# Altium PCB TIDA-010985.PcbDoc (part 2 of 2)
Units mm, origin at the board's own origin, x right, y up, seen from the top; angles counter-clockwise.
Board outline 125.73 x 87.63 mm, 4 copper layers (Top Layer, Signal Layer 1, Signal Layer 2, Bottom Layer), stack 1.565 mm thick; 149 components, 77 nets, 379 pads, 230 vias.
Unrouted connection lines stored in the file: 1.
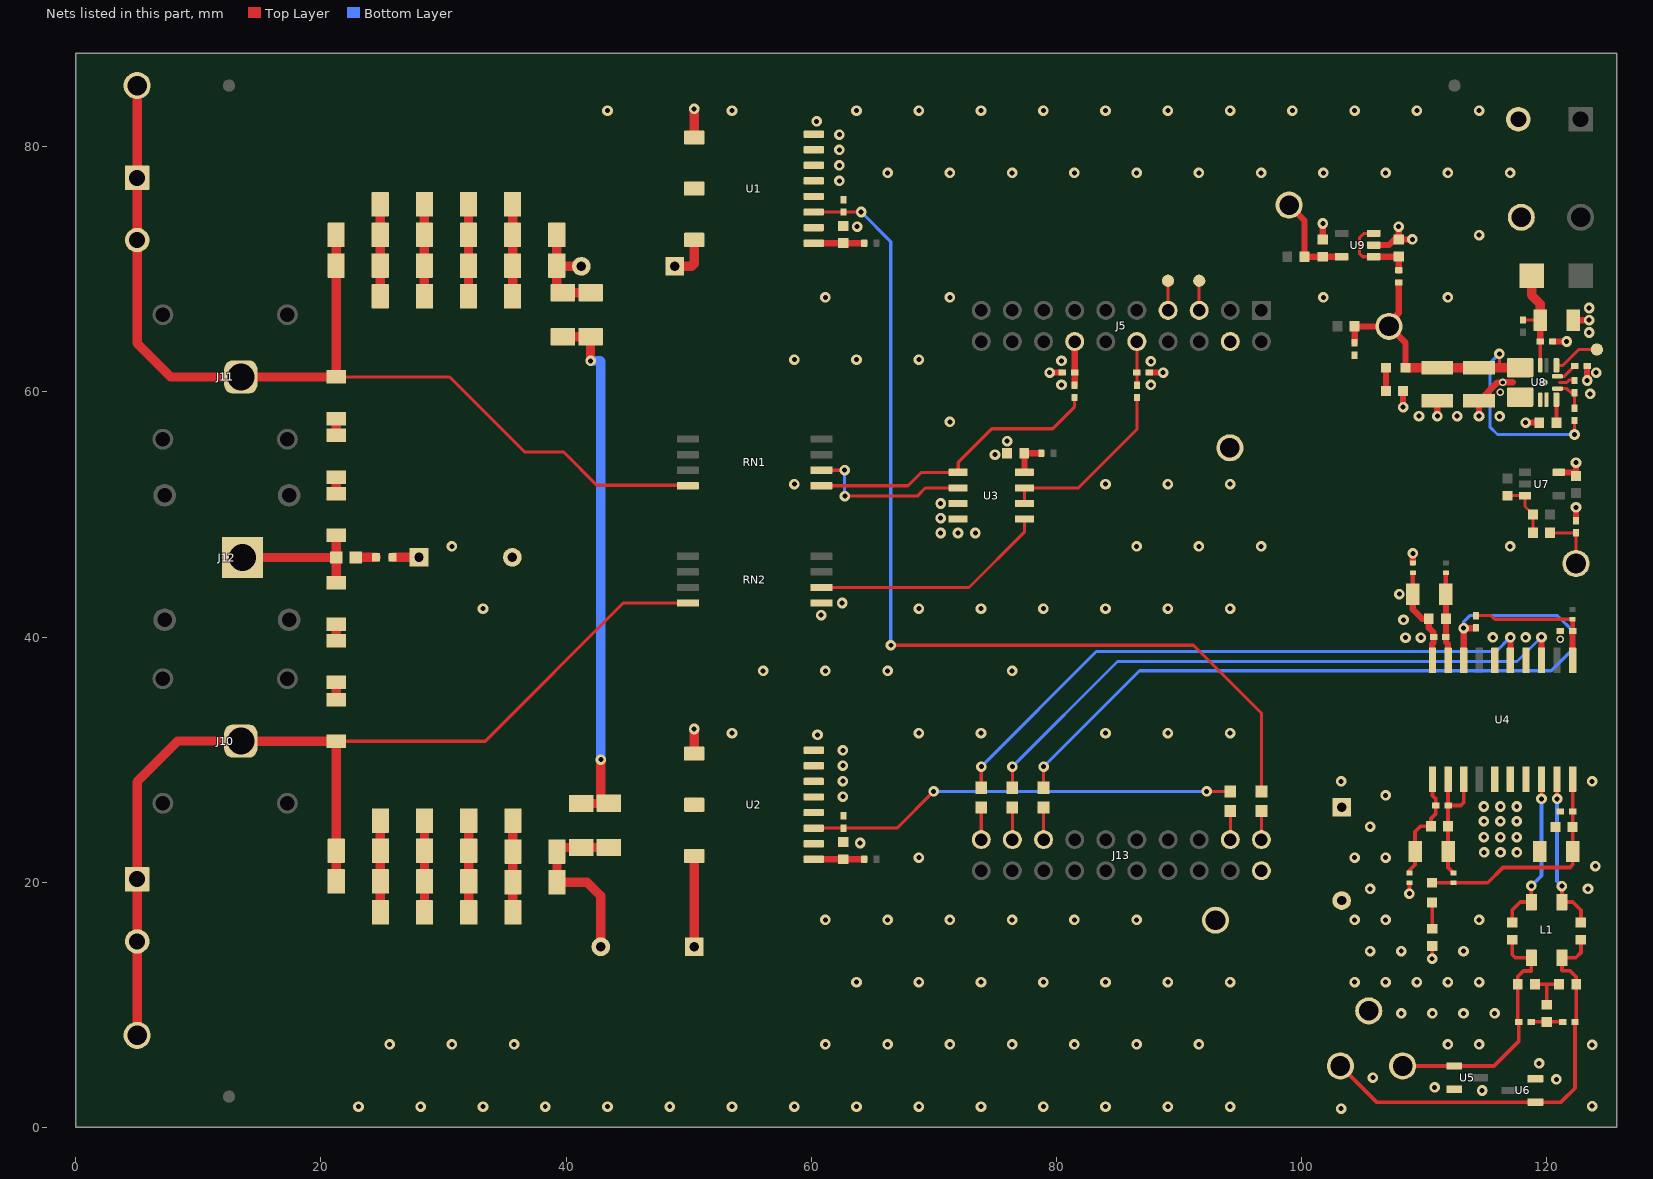
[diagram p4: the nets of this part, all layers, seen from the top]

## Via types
v1: diameter 0.864, hole 0.406, Top Layer to Bottom Layer, tented both sides, 225 vias
v2: diameter 0.61, hole 0.356, Top Layer to Bottom Layer, tented both sides, 5 vias

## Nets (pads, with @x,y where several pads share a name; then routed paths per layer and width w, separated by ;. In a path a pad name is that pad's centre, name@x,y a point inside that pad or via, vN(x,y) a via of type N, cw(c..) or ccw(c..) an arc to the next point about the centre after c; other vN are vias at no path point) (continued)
BUCK_FB: R48.1 R50.2 U8.9 | length 2.8
  Top Layer w0.254: U8.9@120.9,60.273 121.669,60.273 122.009,59.933 R50.2@122.292,59.933 R48.1@122.292,58.673
BUCK_MODE: R49.1 U8.11 | length 1.8
  Top Layer w0.254: U8.11@120.9,61.273 121.463,61.273 R49.1@122.317,62.127
BUCK_OUT: C33.1 C34.1 C35.2 D3.2 FB13.1 R48.2 R52.1 TP3.1 U8.4 | length 37.1
  Top Layer w0.254: 116.158,61.973 v1(116.158,63.113) ; v1(122.292,56.525) R48.2@122.292,57.673
  Top Layer w0.508: C35.2@104.35,64.002 R52.1@104.35,65.352 TP3.1@107.15,65.352 ; FB13.1@107.942,68.929 107.942,66.441 107.15,65.65 TP3.1@107.15,65.352 ; D3.2@108.509,61.973 D3.2@108.5,61.982 108.5,64.002 TP3.1@107.15,65.352
  Top Layer w0.762: D3.2@108.509,61.973 C34.1@111.092,61.973 C33.1@114.5,61.973 116.158,61.973 U8.4@117.85,61.973
  Bottom Layer w0.254: v1(116.158,63.113) 115.388,62.344 115.388,57.149 116.013,56.525 v1(122.292,56.525)
BUCK_PGOOD: TP12.1 U8.1 | length 3.9
  Top Layer w0.254: U8.1@120.882,62.243 U8.1@120.812,62.173 121.35,62.173 122.637,63.459 TP12.1@124.114,63.459
BUCK_VCC: C28.2 U8.8 | length 1.9
  Top Layer w0.305: C28.2@120.812,57.5 U8.8@120.812,59.373
BUCK_VIN: C29.1 C30.2 D2.1 R44.2 U8.3 | length 9.1
  Top Layer w0.254: R44.2@118.08,65.877 119.475,65.877 C29.1@119.5,65.852
  Top Layer w0.305: U8.3@119.5,62.173 119.5,62.503 C30.2@119.5,64.116
  Top Layer w0.508: C30.2@119.5,64.116 C29.1@119.5,65.852
  Top Layer w0.762: D2.1@118.79,69.5 118.79,67.885 119.5,67.175 C29.1@119.5,65.852
CAN_EN: R26.1 R37.1 U4.8 | length 64.1
  Top Layer w0.254: R37.1@78.964,27.7 v1(78.964,29.424)
  Top Layer w0.508: U4.8@113.247,38.1 v1(113.247,40.725) 114.225,40.725 R26.1@114.25,40.75
  Bottom Layer w0.254: v1(78.964,29.424) 86.791,37.25 120.387,37.25 122.137,39 122.137,40.513 120.9,41.75 113.75,41.75 113.247,41.247 v1(113.247,40.725)
CAN_GND1: C6.2 C7.2 C8.2 C12.2 FB12.2 U4.4 U4.6 U4.10 | length 8.2
  Top Layer w0.381: C6.2@109.097,43.5 FB12.2@109.097,45.25
  Top Layer w0.508: C6.2@109.097,43.5 109.097,42.255 109.852,41.5 C7.2@110.397,41.5 110.397,40.746 110.793,40.35 C8.2@110.793,40 110.793,39.544 110.672,39.423 110.672,38.135 U4.10@110.707,38.1
  other v1: 108.499,39.953 109.749,39.953 115.624,39.977 118.307,39.977 108.337,41.41 108,43.504
  other v2: 121.137,39.821
CAN_GND2: C13.2 C14.2 C15.2 FB11.1 U4.11 | length 9.2
  Top Layer w0.305: FB11.1@108.822,20.75 108.822,20.963 109.277,21.418 C15.2@109.277,22.5 109.277,24.107 109.725,24.555 C14.2@110.577,24.555 110.577,25.192 110.977,25.592 C13.2@110.977,26.25 110.977,26.777 110.707,27.047 U4.11@110.707,28.4
CAN_VDD: C6.1 C7.1 C8.1 FB8.2 U4.9 | length 7.2
  Top Layer w0.381: C6.1@111.793,43.504 FB8.2@111.793,45.25
  Top Layer w0.508: C6.1@111.793,43.504 C6.1@111.797,43.5 C7.1@111.797,41.5 111.793,41.496 C8.1@111.793,40 111.793,39.607 111.977,39.423 U4.9@111.977,38.1
CAN_VIO: C12.1 FB9.2 R26.2 U4.1 | length 11.4
  Top Layer w0.254: R26.2@114.25,41.75 115.475,41.75 115.774,41.451 FB9.2@122.137,41.451
  Top Layer w0.381: C12.1@122.137,40.5 FB9.2@122.137,41.451
  Top Layer w0.508: U4.1@122.137,38.1 C12.1@122.137,40.5
CANH: L1.1 R27.2 U4.19 | length 13
  Top Layer w0.305: v1(120.867,26.792) U4.19@120.867,28.4 ; v1(121.266,19.68) L1.1@121.266,18.374 122.143,18.374 122.816,17.701 R27.2@122.816,16.7
  Bottom Layer w0.305: v1(120.867,26.792) 120.867,20.079 v1(121.266,19.68)
CANHI: C16.1 L1.4 R27.1 R28.2 TP13.1 U6.1 | length 35.1
  Top Layer w0.305: TP13.1@103.184,5 106.134,2.05 U6.1@119.1,2.05 121.196,2.05 122.336,3.19 C16.1@122.336,8.6 122.438,8.701 R28.2@122.438,11.672 122.438,12.262 121.934,12.766 121.318,12.766 121.266,12.818 L1.4@121.266,13.824 122.389,13.824 122.816,14.25 R27.1@122.816,15.3
CANL: L1.2 R30.2 U4.18 | length 13.2
  Top Layer w0.305: R30.2@117.216,16.7 117.216,17.729 117.86,18.374 L1.2@118.766,18.374 v1(118.766,19.69) ; v1(119.597,26.792) U4.18@119.597,28.4
  Bottom Layer w0.305: v1(118.766,19.69) 119.597,20.522 v1(119.597,26.792)
CANLO: C18.2 L1.3 R29.1 R30.1 TP14.1 U5.1 | length 20.9
  Top Layer w0.305: TP14.1@108.264,5 U5.1@112.477,5 115.71,5 117.75,7.04 C18.2@117.75,8.6 117.656,8.694 R29.1@117.656,11.672 117.656,12.297 118.11,12.75 118.75,12.75 118.766,12.766 L1.3@118.766,13.824 117.476,13.824 117.216,14.084 R30.1@117.216,15.3
CANRX: R39.1 U4.5 | length 51.1
  Top Layer w0.254: R39.1@73.884,27.7 v1(73.884,29.424)
  Top Layer w0.508: U4.5@117.057,38.1 v1(117.057,39.977)
  Bottom Layer w0.254: v1(73.884,29.424) 83.277,38.816 115.896,38.816 v1(117.057,39.977)
CANTX: R38.1 U4.3 | length 51.2
  Top Layer w0.254: R38.1@76.424,27.7 v1(76.424,29.424)
  Top Layer w0.508: U4.3@119.597,38.1 v1(119.597,40)
  Bottom Layer w0.254: v1(76.424,29.424) 85.001,38 117.597,38 v1(119.597,40)
GND: C1.2 C2.2 C3.2 C4.2 C5.2 C19.2 C22.2 C27.1 C28.1 C29.2 C30.1 C31.2 C32.2 C33.2 C34.2 C35.1 FB12.1 J5.22 J9.2 J13.20 J14.2 R43.1 R49.2 R50.1 R51.1 RN2.5 TP5.1 TP6.1 TP7.1 U1.2 U1.4 U1.5 U1.6 U1.7 U1.8 U1.9 U2.2 U2.4 U2.5 U2.6 U2.7 U2.8 U2.9 U3.3 U3.4 U7.5 U8.10 U9.2 | length 29.9
  Top Layer w0.254: 121.08,60.773 121.65,60.773 121.837,60.96 122.265,60.96 R50.1@122.292,60.933
  Top Layer w0.508: v1(79.466,61.576) C22.2@80.504,61.576 ; C19.2@87.584,61.576 v1(88.718,61.576) ; C32.2@101.75,72.438 v1(101.75,73.746) ; U9.2@105.892,71.984 107.15,71.984 107.613,72.446 C31.2@107.942,72.446 ; v1(107.942,73.496) C31.2@107.942,72.446 ; v1(108.3,58.76) R51.1@108.3,60.077 ; v1(109.06,72.446) C31.2@107.942,72.446 ; FB12.1@109.097,46.05 v1(109.097,46.835) ; v1(111.092,58.025) C34.2@111.092,59.273 ; v1(114.5,58.025) C33.2@114.5,59.273 116,60.773 v2(116.425,60.773) ; v1(118.3,57.5) C28.1@119.412,57.5 ; C30.1@120.5,64.116 v1(121.65,64.116) ; U7.5@121,53.438 122.124,53.438 R43.1@122.412,53.15 v1(122.412,54.225) ; C29.2@122.2,65.852 v1(123.482,65.852) ; C27.1@122.412,49.5 v1(122.412,50.589) ; v1(123.317,60.933) R49.2@123.317,62.127
  Top Layer w0.533: v2(116.425,60.773) 117.234,60.773
  Top Layer w0.762: U2.9@50.46,30.485 v1(50.46,32.5) ; U1.9@50.46,80.757 v1(50.46,83.107)
  other v1: 23.063,1.676 28.143,1.676 33.223,1.676 38.303,1.676 43.383,1.676 48.463,1.676 53.543,1.676 58.623,1.676 63.703,1.676 68.783,1.676 73.863,1.676 78.943,1.676 84.023,1.676 89.103,1.676 94.183,1.676 25.603,6.756 30.683,6.756 35.763,6.756 61.163,6.756 66.243,6.756 71.323,6.756 76.403,6.756 81.483,6.756 86.563,6.756 91.643,6.756 63.703,11.836 68.783,11.836 73.863,11.836 78.943,11.836 84.023,11.836 89.103,11.836 94.183,11.836 61.163,16.916 66.243,16.916 71.323,16.916 76.403,16.916 81.483,16.916 86.563,16.916 68.783,21.996 64,23.193 62.582,26.972 62.582,28.242 62.582,29.5 62.582,30.75 60.521,32.025 53.543,32.156 68.783,32.156 73.863,32.156 84.023,32.156 89.103,32.156 94.183,32.156 56.083,37.236 61.163,37.236 66.243,37.236 76.403,37.236 60.816,41.786 33.223,42.316 68.783,42.316 73.863,42.316 78.943,42.316 84.023,42.316 89.103,42.316 94.183,42.316 62.537,42.775 30.683,47.396 86.563,47.396 91.643,47.396 96.723,47.396 117.043,47.396 70.566,48.493 71.981,48.493 73.395,48.493 70.566,49.696 70.566,50.898 58.623,52.476 84.023,52.476 89.103,52.476 94.183,52.476 75,54.885 76,55.981 71.323,57.556 109.6,58.025 112.722,58.025 116.175,58.008 123.567,59.841 80.428,60.573 87.718,60.585 124.05,61.576 87.718,62.503 80.428,62.541 58.623,62.636 63.703,62.636 68.783,62.636 123.482,64.852 123.482,66.852 61.163,67.716 71.323,67.716 101.803,67.716 111.963,67.716 114.503,72.796 63.75,73.496 62.307,77.222 66.243,77.876 71.323,77.876 76.403,77.876 81.483,77.876 86.563,77.876 91.643,77.876 96.723,77.876 101.803,77.876 106.883,77.876 111.963,77.876 117.043,77.876 62.307,78.492 62.307,79.75 62.307,81 60.443,82.083 43.383,82.956 53.543,82.956 63.703,82.956 68.783,82.956 73.863,82.956 78.943,82.956 84.023,82.956 89.103,82.956 94.183,82.956 99.263,82.956 104.343,82.956 109.423,82.956 114.503,82.956
  other v2: 116.236,59.964
GND_ISO_CAN: C9.2 C10.2 C11.2 C16.2 C17.1 C18.1 FB11.2 J4.1 J4.2 R25.1 TP15.1 U4.15 U4.16 U4.17 U5.2 U6.2 | length 4.5
  Top Layer w0.305: v1(108.822,19.056) FB11.2@108.822,19.95 ; v1(110.672,13.75) R25.1@110.672,14.799 ; C18.1@118.75,8.6 C17.1@120.016,8.6 C16.2@121.336,8.6
  other v1: 103.25,1.514 123.737,1.72 114.75,3 110.879,3.25 120.812,3.905 105.841,4.05 119.397,5.22 123.737,6.72 111.963,6.756 114.503,6.756 108.153,9.296 110.693,9.296 113.233,9.296 115.773,9.296 104.343,11.836 106.883,11.836 109.423,11.836 111.963,11.836 114.503,11.836 105.613,14.376 108.153,14.376 113.233,14.376 104.343,16.916 106.883,16.916 114.503,16.916 105.613,19.456 123.393,19.456 123.987,21.306 104.343,21.996 106.883,21.996 114.911,22.438 116.252,22.438 117.594,22.438 114.895,23.668 116.237,23.668 117.578,23.668 105.613,24.536 114.895,24.97 116.237,24.97 117.578,24.97 114.895,26.174 116.237,26.174 117.578,26.174 106.883,27.076 103.25,28.22 123.737,28.219
LDO_IN: C31.1 FB13.2 U9.1 U9.3 | length 7
  Top Layer w0.254: U9.1@105.892,71.034 104.998,71.034 104.75,71.281 104.75,72.593 105.09,72.934 U9.3@105.892,72.934
  Top Layer w0.508: U9.1@105.892,71.034 107.929,71.034 C31.1@107.942,71.047 FB13.2@107.942,69.929
LDO_OUT: C32.1 R46.1 TP4.1 U9.5 | length 7.8
  Top Layer w0.254: C32.1@101.75,71.038 C32.1@101.754,71.034
  Top Layer w0.508: TP4.1@99,75.25 100.25,74 R46.1@100.25,71.038 C32.1@101.75,71.038 ; C32.1@101.754,71.034 U9.5@103.292,71.034
MP_1: U1.10
MP_2: U2.10
NetC17_2: C17.2 R28.1 R29.2 | length 3.7
  Top Layer w0.305: R29.2@119.056,11.672 120,11.672 ; C17.2@120.016,10 120.016,11.656 120,11.672 ; R28.1@121.038,11.672 120,11.672
NetC20_2: C20.2 C23.1 | length 1.4
  Top Layer w0.762: C20.2@21.25,34.9 C23.1@21.25,36.3
NetC21_2: C21.2 C24.1 | length 1.4
  Top Layer w0.762: C24.1@21.25,56.45 C21.2@21.25,57.825
NetC23_2: C23.2 C25.1 | length 1.4
  Top Layer w0.762: C23.2@21.25,39.7 C25.1@21.25,41.05
NetC24_2: C24.2 C26.1 | length 1.3
  Top Layer w0.762: C26.1@21.25,51.7 C24.2@21.25,53.05
NetD1_1: D1.1 R25.2 | length 2.2
  Top Layer w0.305: R25.2@110.672,16.199 D1.1@110.672,18.35
NetD3_1: D3.1 R51.2 | length 1.9
  Top Layer w0.508: R51.2@106.9,60.077 D3.1@106.9,61.982
NetFB14_2: FB14.2 J9.1 | length 2.2
  Top Layer w0.762: FB14.2@25.85,46.5 J9.1@28,46.5
NetR1_2: R1.2 R2.1 R13.2 R14.1 | length 7.5
  Top Layer w0.762: R14.1@24.84,67.81 R13.2@24.84,70.31 R1.2@24.84,72.81 R2.1@24.84,75.31
NetR2_2: R2.2 R3.1 R14.2 R15.1 | length 7.5
  Top Layer w0.762: R14.2@28.44,67.81 R15.1@28.44,70.31 R3.1@28.44,72.81 R2.2@28.44,75.31
NetR3_2: R3.2 R4.1 R15.2 R16.1 | length 7.5
  Top Layer w0.762: R16.1@32.04,67.81 R15.2@32.04,70.31 R3.2@32.04,72.81 R4.1@32.04,75.31
NetR4_2: R4.2 R5.1 R16.2 R17.1 | length 7.5
  Top Layer w0.762: R16.2@35.64,67.81 R17.1@35.64,70.31 R5.1@35.64,72.81 R4.2@35.64,75.31
NetR6_2: R6.2 R7.1 R18.2 R19.1 | length 42.7
  Top Layer w0.762: R18.2@39.75,64.5 R6.2@42,64.5 v1(42,62.541) ; R19.1@41.25,26.423 42.75,26.423 42.84,26.512 v1(42.84,30)
  Bottom Layer w0.762: v1(42,62.541) 42.799,62.541 42.84,62.5 v1(42.84,30)
NetR8_2: R8.2 R9.1 R20.2 R21.1 | length 7.5
  Top Layer w0.762: R9.1@35.66,17.526 R8.2@35.66,20 R20.2@35.66,22.5 R21.1@35.66,25.026
NetR9_2: R9.2 R10.1 R21.2 R22.1 | length 7.5
  Top Layer w0.762: R9.2@32.06,17.526 R10.1@32.06,20.061 R22.1@32.06,22.561 R21.2@32.06,25.026
NetR10_2: R10.2 R11.1 R22.2 R23.1 | length 7.5
  Top Layer w0.762: R11.1@28.45,17.526 R23.1@28.45,25.019
NetR11_2: R11.2 R12.1 R23.2 R24.1 | length 7.5
  Top Layer w0.762: R11.2@24.85,17.526 R12.1@24.85,20.061 R24.1@24.85,22.561 R23.2@24.85,25.019
OPAMP_V+: C5.1 FB7.2 U3.8 | length 2.8
  Top Layer w0.508: C5.1@77.393,55 FB7.2@78.785,55 ; U3.8@77.4,53.438 C5.1@77.4,54.885
PA8_UART1-TX: J5.4 TP9.1 | length 2.4
  Top Layer w0.254: J5.4@89.124,66.656 TP9.1@89.124,69.069
PA9_UART1-RX: J5.3 TP8.1 | length 2.4
  Top Layer w0.254: J5.3@91.664,66.656 TP8.1@91.664,69.069
PA11: J13.33 R37.2 | length 2.6
  Top Layer w0.254: J13.33@78.964,23.476 R37.2@78.964,26.1
PA12_CAN-TX: J13.32 R38.2 | length 2.6
  Top Layer w0.254: J13.32@76.424,23.476 R38.2@76.424,26.1
PA13_CAN-RX: J13.31 R39.2 | length 2.6
  Top Layer w0.254: J13.31@73.884,23.476 R39.2@73.884,26.1
PA24_ADC0.3: C22.1 J5.27 R34.2 | length 3.6
  Top Layer w0.508: R34.2@81.504,60.547 C22.1@81.504,61.576 J5.27@81.504,64.116
PB1_TIMA1-C1: J13.39 R36.2 | length 2.3
  Top Layer w0.254: J13.39@94.204,23.476 R36.2@94.204,25.806
PB4_TIMA1-C0: J13.40 R35.2 | length 2.3
  Top Layer w0.254: J13.40@96.744,23.476 R35.2@96.744,25.806
PB18_ADC1.5: C19.1 J5.25 R33.2 | length 3.6
  Top Layer w0.254: R33.2@86.584,60.547 C19.1@86.584,61.576 J5.25@86.584,64.116
PE: C25.2 C26.2 J12.1 R45.1 | length 11.5
  Top Layer w0.762: J12.1@13.61,46.49 R45.1@21.24,46.49 R45.1@21.25,46.5 ; C25.2@21.25,44.45 R45.1@21.25,46.5 ; C26.2@21.25,48.3 R45.1@21.25,46.5
PE_R: FB14.1 R45.2 | length 1.7
  Top Layer w0.762: R45.2@22.84,46.49 22.85,46.5 FB14.1@24.5,46.5
S1_U1: J1.1 U1.11 | length 3.6
  Top Layer w0.762: J1.1@48.87,70.25 50.25,70.25 50.46,70.46 U1.11@50.46,72.417
S1_U2: J2.1 U2.11 | length 7.4
  Top Layer w0.762: J2.1@50.46,14.728 U2.11@50.46,22.145
SW_EN1: C3.1 R35.1 U1.3 | length 79.1
  Top Layer w0.254: U1.3@60.21,74.682 C3.1@62.632,74.682 v1(64.085,74.682) ; v1(66.5,39.331) 91.197,39.331 96.744,33.784 R35.1@96.744,27.406
  Bottom Layer w0.254: v1(64.085,74.682) 66.5,72.267 v1(66.5,39.331)
SW_EN2: C4.1 R36.1 U2.3 | length 35.2
  Top Layer w0.254: U2.3@60.21,24.41 C4.1@62.632,24.41 67.004,24.41 v1(70,27.406) ; v1(92.27,27.406) R36.1@94.204,27.406
  Bottom Layer w0.254: v1(70,27.406) v1(92.27,27.406)
TLV431_CAT: R40.2 R41.2 R42.2 U7.3 | length 4.7
  Top Layer w0.254: R40.2@116.824,51.538 U7.3@118.25,51.538 118.25,50.647 R42.2@118.897,50 R41.2@118.897,48.5
U3A_IN-: RN1.6 U3.2 | length 13.5
  Top Layer w0.254: RN1.6@60.835,53.615 v1(62.735,53.615) ; v1(62.75,51.5) 68.655,51.5 69.323,52.168 U3.2@72,52.168
  Bottom Layer w0.254: v1(62.735,53.615) 62.735,51.515 v1(62.75,51.5)
U3B_IN+: RN2.6 U3.5 | length 19.5
  Top Layer w0.254: RN2.6@60.835,44.046 72.888,44.046 77.4,48.558 U3.5@77.4,49.628
VBOOT: U8.7
VDC+: C20.1 J6.1 J6.2 J10.1 R12.2 R24.2 RN2.4 TP11.1 | length 83.1
  Top Layer w0.254: C20.1@21.25,31.5 33.404,31.5 44.68,42.776 RN2.4@49.935,42.776
  Top Layer w0.762: TP11.1@5,7.5 J6.2@5,15.16 J6.1@5,20.24 5,28.2 8.315,31.515 J10.1@13.46,31.515 13.475,31.5 C20.1@21.25,31.5 R24.2@21.25,22.561 R12.2@21.25,20.061
VDC-: C21.1 J7.1 J7.2 J11.1 R1.1 R13.1 RN1.4 TP10.1 | length 82.4
  Top Layer w0.254: C21.1@21.25,61.225 30.5,61.225 36.628,55.098 39.804,55.098 42.513,52.388 49.892,52.388 RN1.4@49.935,52.345
  Top Layer w0.762: TP10.1@5,85 J7.1@5,77.475 J7.2@5,72.395 5,63.975 7.75,61.225 J11.1@13.46,61.225 C21.1@21.25,61.225 21.25,70.3 R13.1@21.24,70.31 R1.1@21.24,72.81
VDD_U1: C1.1 FB1.2 U1.1 | length 4.1
  Top Layer w0.508: U1.1@60.21,72.142 62.735,72.142 FB1.2@64.335,72.142
VDD_U2: C2.1 FB2.2 U2.1 | length 4.1
  Top Layer w0.508: U2.1@60.21,21.87 C2.1@62.632,21.87 FB2.2@64.335,21.87
VEREF+: C27.2 R41.1 TP1.1 | length 4.6
  Top Layer w0.254: R41.1@120.297,48.5 C27.2@122.412,48.5 TP1.1@122.412,46
VISOOUT: C13.1 C14.1 C15.1 FB10.1 U4.12 U4.13 | length 11.1
  Top Layer w0.305: U4.12@111.977,28.4 C13.1@111.977,26.25 ; FB10.1@112.422,20.75 111.977,21.195 C15.1@111.977,22.5 C14.1@111.977,24.555 C13.1@111.977,26.25 ; U4.13@113.247,28.4 113.247,26.494 113.003,26.25 C13.1@111.977,26.25
VP_CAN: C9.1 C10.1 C11.1 D1.2 FB10.2 U4.20 | length 19.1
  Top Layer w0.305: D1.2@110.672,19.95 FB10.2@112.422,19.95 115.213,19.95 116.458,21.195 121.914,21.195 122.137,21.418 122.137,26.25 U4.20@122.137,28.4
VSENSE_NEG: R34.1 RN1.5 U3.1 | length 24.6
  Top Layer w0.254: RN1.5@60.835,52.345 67.907,52.345 69,53.438 U3.1@72,53.438 72,54.25 74.75,57 79.703,57 81.504,58.802 R34.1@81.504,59.547
VSENSE_POS: R33.1 U3.6 U3.7 | length 15
  Top Layer w0.254: U3.6@77.4,50.898 U3.7@77.4,52.168 81.806,52.168 86.584,56.946 R33.1@86.584,59.547
VSN_1: J1.2 R5.2 R6.1 R17.2 R18.1 | length 9.2
  Top Layer w0.762: R5.2@39.24,72.81 R17.2@39.24,70.31 ; J1.2@41.25,70.25 39.3,70.25 R17.2@39.24,70.31 ; R6.1@42,68.1 R18.1@39.75,68.1 39.24,68.61 R17.2@39.24,70.31
VSN_2: J2.2 R7.2 R8.1 R19.2 R20.1 | length 15.3
  Top Layer w0.762: J2.2@42.84,14.728 42.84,18.877 41.717,20 R8.1@39.26,20 R20.1@39.26,22.5 39.583,22.823 R19.2@41.25,22.823 R7.2@43.75,22.823
VSW: U8.5 U8.6 | length 0
  Top Layer w0.305: U8.5@117.849,59.572 U8.5@117.85,59.573
pads on no net: FID1.1 FID2.1 FID3.1 J5.2 J5.5 J5.6 J5.7 J5.8 J5.9 J5.10 J5.23 J5.24 J5.26 J5.28 J5.29 J5.30 J10.2 J10.3 J10.4 J10.5 J11.2 J11.3 J11.4 J11.5 J12.2 J12.3 J12.4 J12.5 J13.11 J13.12 J13.13 J13.14 J13.15 J13.16 J13.17 J13.18 J13.19 J13.34 J13.35 J13.36 J13.37 J13.38 LBL1.0 RN1.1 RN1.2 RN1.3 RN1.7 RN1.8 RN2.1 RN2.2 RN2.3 RN2.7 RN2.8 U4.2 U4.7 U4.14 U5.3 U6.3 U7.1 U7.2 U9.4

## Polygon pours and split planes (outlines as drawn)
GND_ISO_CAN on Top Layer "Top Layer-GND_ISO_CAN" (solid, pour order 18): 102.116,0 125.73,0 125.73,29.35 102.116,29.35
GND on Top Layer "Top Layer-GND" (solid, pour order 6): 97.478,44.616 125.73,44.616 125.73,45.493 125.73,87.001 97.75,87 59.75,87 59.75,0 97.478,0
CAN_GND1 on Top Layer "Top Layer-CAN_GND1" (solid, remove dead copper, pour order 8): 107.529,37.124 123,37.124 123,45.5 107.529,45.5
GND_ISO_CAN on Signal Layer 1 "Signal Layer 1-GND_ISO_CAN" (solid, pour order 16): 102.116,0.75 125,0.75 125,29.35 102.116,29.35
GND on Signal Layer 1 "Signal Layer 1-GND" (solid, pour order 2): 125.73,44.75 97.478,44.75 97.478,0 21.25,0 21.25,87.5 125.73,87.5
CAN_GND1 on Signal Layer 1 "Signal Layer 1-CAN_GND1" (solid, pour order 10): 107.529,37.124 123,37.124 123,44.616 107.529,44.616
GND_ISO_CAN on Signal Layer 2 "Signal Layer 2-GND_ISO_CAN" (solid, pour order 20): 102.116,0.75 125,0.75 125,29.35 102.116,29.35
GND on Signal Layer 2 "Signal Layer 2-GND" (solid, pour order 12): 125.5,44.629 97.478,44.629 97.478,0 21.02,0 21.02,87.5 125.5,87.5
CAN_GND1 on Signal Layer 2 "Signal Layer 2-CAN_GND1" (solid, pour order 14): 107.529,37.124 123,37.124 123,44.295 107.529,44.295
GND_ISO_CAN on Bottom Layer "Bottom Layer-GND_ISO_CAN" (solid, pour order 22): 102.116,0.75 125,0.75 125,29.35 102.116,29.35
GND on Bottom Layer "Bottom Layer-GND" (solid, pour order 24): 97.478,45 125.73,45 125.73,45.878 125.73,87.386 97.75,87.384 59.75,87.384 59.75,0.384 97.478,0.384

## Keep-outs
Keep-Out Layer:
  text ".Layer_Name" at 14.656,-21.806 h1.52

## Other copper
Top Layer:
  pour cut-out: 116.775,58.76 121.35,58.76 121.35,62.75 116.775,62.75
  pour cut-out: 117.632,13.349 122.329,13.349 122.329,18.735 117.632,18.735
  pour cut-out: 108.831,20.694 113.888,20.694 113.888,29.33 108.831,29.33
  text ".Layer_Name" at 14.656,-21.806 h1.52
Signal Layer 1:
  pour cut-out: 108.831,20.694 113.888,20.694 113.888,29.33 108.831,29.33
  pour cut-out: 117.632,13.349 122.329,13.349 122.329,18.735 117.632,18.735
Signal Layer 2:
  pour cut-out: 108.831,20.694 113.888,20.694 113.888,29.33 108.831,29.33
  pour cut-out: 117.632,13.349 122.329,13.349 122.329,18.735 117.632,18.735
Bottom Layer:
  pour cut-out: 108.831,20.694 113.888,20.694 113.888,29.33 108.831,29.33
  pour cut-out: 117.632,13.349 122.329,13.349 122.329,18.735 117.632,18.735
  text ".Layer_Name" at 14.656,-21.806 h1.52

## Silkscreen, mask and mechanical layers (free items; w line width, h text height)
Top Overlay:
  lines w0.1: 47.5,40 47.501,39.999
  lines w0.203: 89.124,62.503 47.5,62.503 47.5,40 84.999,39.999 91.664,46.664 91.664,62.503
  text "TPSI2240" at 51.535,83.25 h2.54
  text "INPUT PWR" at 98.604,83.25 h2.54
  text "RES DIV NETWORK" at 25.25,80.75 h1.91
  text "6-36V, 5W" at 98.75,80.413 h2.54
  text "-" at 10.75,77.75 h2.54 r270
  text "-" at 10.75,72.75 h2.54 r270
  text "VDC-" at 14.25,72.142 h2.54 r90
  text "UART / TX   RX" at 88,71.761 h1.52
  text "SSR1" at 53.051,68.31 h2.54
  text "5V" at 109.596,65.25 h2.54
  text "-" at 80.504,60.166 h2.54 r180
  text "RES60A" at 53,59 h2.54
  text "+" at 89,58.998 h2.54 r90
  text "ADC0" at 78.065,57.766 h1.52
  text "ADC1" at 86.065,57.766 h1.52
  text "GND" at 34.895,48 h2.54
  text "PE" at 24.7,47.969 h2.54
  text "TLV9002" at 75.25,46.75 h1.91
  text "3.3VREF" at 114.986,43.75 h1.52
  text "VOLTAGE SENSE" at 68.918,41.75 h1.91
  text "ISO CAN" at 104.5,37.25 h1.91 r270
  text "ISOW1044" at 107,37.25 h1.91 r270
  text "CANRX" at 74.064,33.312 h1.02 r90
  text "CANTX" at 76.659,33.312 h1.02 r90
  text "CANEN" at 79.357,33.312 h1.02 r90
  text "TPSI2240" at 51.547,33 h2.54
  text "EN2" at 90.5,32 h1.91
  text "EN1" at 97.551,32 h1.91
  text "+" at 11.75,19.69 h2.54 r90
  text "SSR2" at 52.75,17.845 h2.54
  text "VDC+" at 14.25,14.799 h2.54 r90
  text "+" at 11.75,14.5 h2.54 r90
  text "RES DIV NETWORK" at 25.25,11.75 h1.91
  text "VBUS 0-1kV" at 17.75,8 h2.54 r90
  text "'.PRJ_Number' .PCB_Rev" at 37.5,8 h2.75
  text "GND" at 104.75,6.72 h1.02
  text "CAN" at 92.962,4.106 h2.54
  text "CANH" at 102.116,2.05 h1.02
  text "CANL" at 107.25,2.05 h1.02
  text ".Layer_Name" at 14.656,-21.806 h1.52
Bottom Overlay:
  text ".Layer_Name" at 14.656,-21.806 h1.52
Top Paste:
  text ".Layer_Name" at 14.656,-21.806 h1.52
Bottom Paste:
  text ".Layer_Name" at 14.656,-21.806 h1.52
Top Solder:
  text ".Layer_Name" at 14.656,-21.806 h1.52
  text ".Layer_Name" at 14.656,-21.806 h1.52
Bottom Solder:
  text ".Layer_Name" at 14.656,-21.806 h1.52
Drill Guide:
  text ".Layer_Name" at 14.656,-21.806 h1.52
M1 Board Outline:
  the board outline again, w0.254
  text ".Layer_Name" at 14.656,-21.806 h1.52
M2 Board Dimensions:
  rectangle: 0,-6.985 3.175,-3.81
  rectangle: 3.175,-10.16 12.7,-6.985
  lines w0.178: 0,-6.985 25.4,-6.985 ; 3.175,-10.16 3.175,-3.81 ; 6.35,-10.16 6.35,-3.81 ; 12.7,-10.16 12.7,-3.81 ; 19.05,-10.16 19.05,-3.81 ; 0,-10.16 25.4,-10.16 25.4,-3.81 0,-3.81 0,-10.16
  text ".Layer_Name" at 14.656,-21.806 h1.52
M3 3D STEP Top:
  text ".Layer_Name" at 14.656,-21.806 h1.52
M4 3D STEP Bottom:
  text ".Layer_Name" at 14.656,-21.806 h1.52
M5 Assembly Top:
  lines w0.254: -7.417,-23.626 160.223,-23.626 ; -7.417,-18.462 160.274,-18.462 ; -7.417,-13.297 -7.417,-28.791 94.31,-28.791 160.274,-28.791 160.274,-13.297 -7.404,-13.297 -7.404,-28.791 32.614,-28.791 ; 55.194,-28.791 55.194,-13.297 ; 87.376,-18.462 87.376,-13.297 ; 108.712,-18.462 108.712,-13.297 ; 124.511,-28.956 124.511,-23.804
  text "COMPONENTS MARKED 'DNP' SHOULD NOT BE POPULATED." at 29.299,-8.09 h1.52
  text "ASSEMBLY VARIANT:" at 29.286,-11.024 h1.52
  text ".VariantName" at 55.601,-11.024 h1.52
  text "PCB VIEWED FROM TOP SIDE" at -5.804,-16.654 h1.52
  text "BOARD #:" at 57.099,-16.654 h1.52
  text ".PRJ_Number" at 70.955,-16.654 h1.52
  text "REV:" at 92.405,-16.654 h1.52
  text ".PCB_Rev" at 99.809,-16.654 h1.52
  text "SVN REV:" at 113.69,-16.654 h1.52
  text ".VersionControl_RevNumber" at 126.543,-16.654 h1.52
  text "TID #:" at 57.099,-21.819 h1.52
  text ".TID" at 70.955,-21.819 h1.52
  text "PLOT NAME =" at -5.804,-27.034 h1.52
  text ".plot_File_Name" at 14.656,-27.034 h1.52
  text "GENERATED    :" at 57.15,-27.034 h1.52
  text ".Print_Date" at 79.235,-27.034 h1.52
  text ".Print_Time" at 97.752,-27.034 h1.52
  text "TEXAS INSTRUMENTS" at 129.87,-27.034 h1.52
M6 Assembly Bottom:
  lines w0.254: -7.429,-18.474 160.261,-18.474 ; -7.379,-23.639 160.261,-23.639 ; 28.334,-28.969 28.334,-23.817 ; 44.133,-18.474 44.133,-13.31 ; 65.468,-18.474 65.468,-13.31 ; 97.65,-28.804 97.65,-13.31 ; 120.231,-28.804 160.249,-28.804 160.249,-13.31 -7.429,-13.31 -7.429,-28.804 58.534,-28.804 160.261,-28.804 160.261,-13.31
  text "COMPONENTS MARKED 'DNP' SHOULD NOT BE POPULATED." at 154.991,-8.077 h1.52
  text ".VariantName" at 128.473,-11.024 h1.52
  text "ASSEMBLY VARIANT:" at 154.864,-11.024 h1.52
  text ".VersionControl_RevNumber" at 26.302,-16.667 h1.52
  text "SVN REV:" at 39.154,-16.667 h1.52
  text ".PCB_Rev" at 53.035,-16.667 h1.52
  text "REV:" at 60.439,-16.667 h1.52
  text ".PRJ_Number" at 81.89,-16.667 h1.52
  text "BOARD #:" at 95.745,-16.667 h1.52
  text "PCB VIEWED FROM BOTTOM SIDE" at 158.648,-16.667 h1.52
  text ".TID" at 81.89,-21.831 h1.52
  text "TID #:" at 95.745,-21.831 h1.52
  text "TEXAS INSTRUMENTS" at 22.974,-27.047 h1.52
  text ".Print_Time" at 55.093,-27.047 h1.52
  text ".Print_Date" at 73.609,-27.047 h1.52
  text "GENERATED    :" at 95.694,-27.047 h1.52
  text ".plot_File_Name" at 138.189,-27.047 h1.52
  text "PLOT NAME =" at 158.648,-27.047 h1.52
M9 Title Sheet:
  drawing of 57 lines, arcs and shapes, not listed
  text "1" at 18.792,204.127 h1.78
  text "2" at 82.182,204.127 h1.78
  text "3" at 145.411,204.127 h1.78
  text "4" at 209.08,204.127 h1.78
  text "5" at 272.555,204.127 h1.78
  text "6" at 336.182,204.127 h1.78
  text "A" at -10.579,175.095 h1.78
  text "A" at 365.341,175.095 h1.78
  text "B" at -10.579,114.643 h1.78
  text "B" at 365.341,114.643 h1.78
  text "C" at -10.579,54.318 h1.78
  text "C" at 365.341,54.318 h1.78
  text "PROJECT TITLE:" at 288.125,7.048 h1.14
  text ".PRJ_Title" at 289.395,3.662 h1.78
  text "DESIGNED FOR:" at 288.125,-0.597 h1.14
  text ".PRJ_Customer" at 289.395,-4.153 h1.78
  text "D" at -10.579,-5.88 h1.78
  text "D" at 365.341,-5.88 h1.78
  text "FILE NAME:" at 288.125,-8.217 h1.14
  text ".PCB_File_Name_No_Path" at 289.395,-11.265 h1.78
  text "Texas Instruments (TI) and/or its licensors do not warrant the accuracy or completeness of this specification" at 161.9,-15.376 h1.14
  text "ENGINEER:" at 288.125,-15.583 h1.14
  text "LAYOUT BY:" at 326.352,-15.583 h1.14
  text "or any information contained therein. TI and/or its licensors do not warrant that this design will meet" at 160.757,-18.237 h1.14
  text ".PRJ_Engineer" at 289.395,-19.52 h1.78
  text ".PCB_Layout" at 327.635,-19.52 h1.78
  text "the specifications, will be suitable for your application or fit for any particular purpose, or will operate in" at 160.757,-21.099 h1.14
  text ".Layer_Name" at 14.656,-21.806 h1.52
  text "ALTIUM DESIGNER VERSION:" at 326.352,-23.457 h1.14
  text "an implementation. TI and/or its licensors do not warrant that the design is production worthy. You should" at 160.757,-23.961 h1.14
  text "completely validate and test your design implementation to confirm the system functionality for your application." at 161.9,-26.822 h1.14
  text ".print_Scale" at 289.395,-26.843 h1.78
  text ".Application_BuildNumber" at 327.635,-26.843 h1.78
  text "1" at 18.792,-32.093 h1.78
  text "2" at 82.182,-32.093 h1.78
  text "3" at 145.411,-32.093 h1.78
  text "4" at 209.08,-32.093 h1.78
  text "5" at 272.555,-32.093 h1.78
  text "6" at 336.182,-32.093 h1.78
M10 Fab Notes:
  drawing of 189 lines, arcs and shapes, not listed
  text "DESIGN INFORMATION" at 314.503,161.447 h1.52
  text "MIN. TRACK WIDTH:" at 298.131,158.091 h1.52
  text "10" at 325.976,158.091 h1.52
  text "MIL" at 329.907,158.091 h1.52
  text "MIN. CLEARANCE:" at 298.131,154.938 h1.52
  text "MIL" at 329.907,154.938 h1.52
  text "4.5" at 324.5,154.75 h1.52
  text "MIN. VIA PAD SIZE:" at 298.131,151.785 h1.52
  text "24" at 325.214,151.785 h1.52
  text "MIL" at 329.907,151.785 h1.52
  text "0.127mm (5MIL)" at 315.784,148.486 h1.52
  text "MINIMUM ANNULAR RING" at 289.769,148.277 h1.52
  text "EXTERNAL" at 333.768,148.277 h1.52
  text "PER" at 294.849,145.48 h1.52
  text "IPC-D-275 CLASS 2 LEVEL C" at 300.437,145.48 h1.52
  text "MIL, HOLES" at 338.238,142.928 h1.52
  text "+/-" at 328.27,142.709 h1.52
  text "+/-" at 349.961,142.709 h1.52
  text "REGISTRATION TOLERANCES:" at 289.769,142.682 h1.52
  text "METAL" at 320.243,142.682 h1.52
  text "5" at 334.879,142.683 h1.52
  text "3" at 356.037,142.683 h1.52
  text "MIL" at 358.99,142.682 h1.52
  text "HOLE SIZE TOLERANCE (UNLESS OTHERWISE SPECIFIED):" at 289.769,140.185 h1.52
  text "+/-" at 349.961,140.112 h1.52
  text "3" at 356.037,140.085 h1.52
  text "MIL" at 358.99,140.085 h1.52
  text "MATERIAL:" at 287.87,136.589 h1.52
  text "FR-4 High Tg" at 312.926,133.324 h1.52
  text "X" at 309.257,133.122 h1.52
  text "FR-4" at 298.563,133.007 h1.52
  text "OTHER" at 336.358,133.007 h1.52
  text "62 MIL (1.6mm) +/-10%" at 306.694,129.374 h1.52
  text "X" at 303.643,129.312 h1.52
  text "THICKNESS:" at 289.769,129.165 h1.52
  text "OTHER" at 339.33,129.165 h1.52
  text "TOLERANCE:" at 289.769,125.652 h1.52
  text "X" at 311.314,125.652 h1.52
  text "ANSI IPC-6012 TYPE 3 CLASS 2" at 315.836,125.652 h1.52
  text "OTHER +/-" at 315.835,121.989 h1.52
  text "BOW & TWIST:" at 289.769,118.302 h1.52
  text "X" at 311.314,118.302 h1.52
  text "ANSI IPC-6012 TYPE 3 CLASS 2" at 315.836,118.302 h1.52
  text "OTHER +/-" at 315.835,114.576 h1.52
  text "DRILLING:" at 287.87,111.258 h1.52
  text "NC_DRILL FILES" at 332.599,108.586 h1.52
  text "REFERENCE:" at 289.769,108.486 h1.52
  text "X" at 306.463,108.484 h1.52
  text "AS SHOWN" at 310.984,108.486 h1.52
  text "X" at 329.348,108.486 h1.52
  text "OTHER" at 340.168,104.873 h1.52
  text "PTH COPPER THICKNESS:" at 289.761,104.783 h1.52
  text "X" at 318.697,104.783 h1.52
  text "20-30 um" at 321.948,104.783 h1.52
  text "BOARD FINISH:" at 287.87,101.034 h1.52
  text "SILKSCREEN:" at 291.812,98.237 h1.52
  text "X" at 316.14,98.237 h1.52
  text "TOP" at 319.112,98.237 h1.52
  text "X" at 329.094,98.237 h1.52
  text "BOTTOM" at 332.091,98.237 h1.52
  text "SILKSCREEN COLOR:" at 291.812,94.295 h1.52
  text "X" at 316.115,94.295 h1.52
  text "WHITE" at 319.112,94.295 h1.52
  text "OTHER" at 332.091,94.295 h1.52
  text "X" at 319.442,90.652 h1.52
  text "GREEN" at 322.439,90.652 h1.52
  text "OTHER" at 338.136,90.652 h1.52
  text "SOLDER RESIST COLOR:" at 291.812,90.477 h1.52
  text "X" at 319.442,86.734 h1.52
  text "MATTE" at 322.439,86.734 h1.52
  text "SEMI-GLOSS" at 338.125,86.717 h1.52
  text "IMMERSION GOLD (ENIG)" at 314.819,82.345 h1.52
  text "ENEPIG" at 348.793,82.162 h1.52
  text "SURFACE FINISH:" at 287.87,82.136 h1.52
  text "X" at 310.298,82.136 h1.52
  text "IMM. TIN/SILVER OR EQUIV" at 296.24,78.649 h1.52
  text "OTHER" at 332.599,78.549 h1.52
  text "ARRAY/PANEL:" at 287.87,74.602 h1.52
  text "CUT AND TRIM PER M1 BOARD OUTLINE" at 314.819,74.393 h1.52
  text "N.C. ROUTE" at 314.819,70.94 h1.52
  text "X" at 332.295,70.94 h1.52
  text "V. SCORE" at 336.816,70.94 h1.52
  text "CERTIFICATION:" at 287.87,67.66 h1.52
  text "MATERIALS AND WORKMANSHIP FOR ALL PCBS" at 306.285,67.66 h1.52
  text "TO MEET OR EXCEED THE REQUIREMENTS OF:" at 306.285,65.271 h1.52
  text "X" at 297.078,62.003 h1.52
  text "ANSI IPC-A-600F CLASS ->" at 300.329,62.003 h1.52
  text "X" at 342.188,62.003 h1.52
  text "2" at 344.982,62.003 h1.52
  text "1" at 336.981,61.965 h1.52
  text "3" at 353.973,61.965 h1.52
  text "X" at 317.702,58.252 h1.52
  text "RoHS" at 320.953,58.252 h1.52
  text "OTHER" at 337.321,58.252 h1.52
  text "PER ORDER" at 347.407,58.252 h1.52
  text "ALL BOARDS MUST MEET OR EXCEED UL94-V0 REQUIREMENTS." at 288.569,54.345 h1.52
  text "PCB MUST BEAR THE UL94V-0 UL REGISTERED MATERIAL ID NUMBER" at 288.569,51.397 h1.52
  text "ADDITIONAL REQUIREMENTS:" at 287.87,47.094 h1.52
  text "MICROSECTION:" at 289.769,44.373 h1.52
  text "YES" at 312.775,44.373 h1.52
  text "REQUIRED" at 334.657,40.707 h1.52
  text "BARE BOARD ELEC. TEST:" at 289.769,40.634 h1.52
  text "NONE" at 322.935,40.634 h1.52
  text "X" at 331.66,40.634 h1.52
  text "PER ORDER" at 349.693,40.634 h1.52
  text "XX MIL VIAS REQUIRE NON-CONDUCTIVE FILL AND PLANARIZE" at 294.04,35.428 h1.5
  text "XX MIL VIAS REQUIRE CONDUCTIVE FILL AND PLANARIZE" at 294.243,32.787 h1.52
  text "OUTER XX MIL TRACES REQUIRE 50 OHM SINGLE-ENDED IMPEDANCE" at 294.218,28.637 h1.47
  text "LAYER 2 & 3 (INNER LAYERS) XX MIL WIDE, XX MIL SPACE / TRACES REQUIRE 100 OHM DIFFERENTIAL IMPEDANCE" at 294.015,22.65 h1.52
  text ".Layer_Name" at 14.656,-21.806 h1.52
M11 Gerber Information:
  lines w0.254: -7.417,-23.626 160.223,-23.626 ; -7.417,-18.462 160.274,-18.462 ; -7.417,-13.297 -7.417,-28.791 94.31,-28.791 160.274,-28.791 160.274,-13.297 -7.404,-13.297 -7.404,-28.791 32.614,-28.791 ; 55.194,-28.791 55.194,-13.297 ; 87.376,-18.462 87.376,-13.297 ; 108.712,-18.462 108.712,-13.297 ; 124.511,-28.956 124.511,-23.804
  text "ALL ARTWORK VIEWED FROM TOP SIDE" at -5.804,-16.654 h1.52
  text "BOARD #:" at 57.099,-16.654 h1.52
  text ".PRJ_Number" at 70.955,-16.654 h1.52
  text "REV:" at 92.405,-16.654 h1.52
  text ".PCB_Rev" at 99.809,-16.654 h1.52
  text "SVN REV:" at 113.69,-16.654 h1.52
  text ".VersionControl_RevNumber" at 126.543,-16.654 h1.52
  text "LAYER NAME =" at -5.804,-21.806 h1.52
  text "TID #:" at 57.099,-21.819 h1.52
  text ".TID" at 70.955,-21.819 h1.52
  text "PLOT NAME =" at -5.804,-27.034 h1.52
  text ".plot_File_Name" at 14.656,-27.034 h1.52
  text "GENERATED    :" at 57.15,-27.034 h1.52
  text ".Print_Date" at 79.235,-27.034 h1.52
  text ".Print_Time" at 97.752,-27.034 h1.52
  text "TEXAS INSTRUMENTS" at 129.87,-27.034 h1.52
M12 Stackup:
  drawing of 295 lines, arcs and shapes, not listed
  text "Layer" at 161.655,153.003 h1.52
  text "Name" at 172.066,153.003 h1.52
  text "Material" at 195.936,153.003 h1.52
  text "Thickness" at 217.774,153.003 h1.52
  text "Constant" at 234.28,153.003 h1.52
  text "Board Layer Stack" at 248.754,153.003 h1.52
  text "1" at 161.655,149.955 h1.52
  text "Top Overlay" at 172.066,149.955 h1.52
  text "2" at 161.655,146.907 h1.52
  text "Top Solder" at 172.066,146.907 h1.52
  text "Solder Resist" at 195.936,146.907 h1.52
  text "0.40mil" at 217.774,146.907 h1.52
  text "3.5" at 234.28,146.907 h1.52
  text "3" at 161.655,143.859 h1.52
  text "Top Layer" at 172.066,143.859 h1.52
  text "Copper" at 195.936,143.859 h1.52
  text "1.40mil" at 217.774,143.859 h1.52
  text "4" at 161.655,140.811 h1.52
  text "Dielectric 1" at 172.066,140.811 h1.52
  text "FR-4 High Tg" at 195.936,140.811 h1.52
  text "8.00mil" at 217.774,140.811 h1.52
  text "4.2" at 234.28,140.811 h1.52
  text "5" at 161.655,137.763 h1.52
  text "Signal Layer 1" at 172.066,137.763 h1.52
  text "Copper" at 195.936,137.763 h1.52
  text "1.40mil" at 217.774,137.763 h1.52
  text "6" at 161.655,134.715 h1.52
  text "Dielectric 2" at 172.066,134.715 h1.52
  text "FR-4 High Tg" at 195.936,134.715 h1.52
  text "40.00mil" at 217.774,134.715 h1.52
  text "4.2" at 234.28,134.715 h1.52
  text "7" at 161.655,131.667 h1.52
  text "Signal Layer 2" at 172.066,131.667 h1.52
  text "Copper" at 195.936,131.667 h1.52
  text "1.40mil" at 217.774,131.667 h1.52
  text "8" at 161.655,128.619 h1.52
  text "Dielectric 3" at 172.066,128.619 h1.52
  text "FR-4 High Tg" at 195.936,128.619 h1.52
  text "8.00mil" at 217.774,128.619 h1.52
  text "4.2" at 234.28,128.619 h1.52
  text "9" at 161.655,125.571 h1.52
  text "Bottom Layer" at 172.066,125.571 h1.52
  text "Copper" at 195.936,125.571 h1.52
  text "1.40mil" at 217.774,125.571 h1.52
  text "10" at 161.655,122.523 h1.52
  text "Bottom Solder" at 172.066,122.523 h1.52
  text "Solder Resist" at 195.936,122.523 h1.52
  text "0.40mil" at 217.774,122.523 h1.52
  text "3.5" at 234.28,122.523 h1.52
  text "11" at 161.655,119.475 h1.52
  text "Bottom Overlay" at 172.066,119.475 h1.52
  text ".Layer_Name" at 14.656,-21.806 h1.52
M13 Component Bodies Top:
  text ".Layer_Name" at 14.656,-21.806 h1.52
M14 Component Bodies Bottom:
  text ".Layer_Name" at 14.656,-21.806 h1.52
M15 Courtyards Top:
  text ".Layer_Name" at 14.656,-21.806 h1.52
M16 Courtyards Bottom:
  text ".Layer_Name" at 14.656,-21.806 h1.52
Drill Drawing:
  circle w0.254: c-3.194,168.49 r0.847
  lines w0.254: -4.041,171.454 -2.347,171.454 -2.347,173.147 -4.041,173.147 -4.041,171.454 ; -4.041,176.957 -2.347,176.957 -3.194,175.264 -4.041,176.957 ; -4.041,179.074 -4.041,179.497 -3.617,179.92 -4.041,180.343 -4.041,180.767 -3.617,180.767 -3.194,180.343 -2.771,180.767 -2.347,180.767 -2.347,180.343 -2.771,179.92 -2.347,179.497 -2.347,179.074 -2.771,179.074 -3.194,179.497 -3.617,179.074 -4.041,179.074 ; -4.041,182.884 -3.194,183.307 -2.347,182.884 -2.771,183.73 -2.347,184.577 -3.194,184.153 -4.041,184.577 -3.617,183.73 -4.041,182.884 ; -4.041,187.117 -3.617,187.117 -3.194,186.694 -2.771,187.117 -2.347,187.117 -2.771,187.54 -2.347,187.963 -2.771,187.963 -3.194,188.387 -3.617,187.963 -4.041,187.963 -3.617,187.54 -4.041,187.117 ; -4.041,190.504 -2.347,190.504 -2.347,192.197 -4.041,192.197 -4.041,190.504 ; -4.041,194.737 -3.617,194.737 -3.617,194.314 -2.771,194.314 -2.771,194.737 -2.347,194.737 -2.347,195.583 -2.771,195.583 -2.771,196.007 -3.617,196.007 -3.617,195.583 -4.041,195.583 -4.041,194.737 ; -3.702,190.842 -2.686,190.842 -2.686,191.858 -3.702,191.858 -3.702,190.842
  lines w0.381: -5.56,166.501 272.696,166.501 ; -5.56,196.981 272.696,196.981 ; 8.433,162.691 8.433,200.791 ; 23.161,162.691 23.161,200.791 ; 51.093,162.691 51.093,200.791 ; 63.942,162.691 63.942,200.791 ; 82.581,162.691 82.581,200.791 ; 120.669,162.691 120.669,200.791 ; 135.651,162.691 135.651,200.791 ; 163.329,162.691 163.329,200.791 ; 182.12,162.691 182.12,200.791 ; 203.806,162.691 203.806,200.791 ; 237.679,162.691 237.679,200.791 ; -5.56,162.691 272.696,162.691 272.696,200.791 -5.56,200.791 -5.56,162.691
  text "Symbol" at -3.274,198.124 h1.83
  text "Count" at 9.576,198.124 h1.83
  text "Hole Size" at 24.304,198.124 h1.83
  text "Plated" at 52.236,198.124 h1.83
  text "Hole Type" at 65.085,198.124 h1.83
  text "Drill Layer Pair" at 83.724,198.124 h1.83
  text "Via/Pad" at 121.812,198.124 h1.83
  text "Pad Shape" at 136.794,198.124 h1.83
  text "Template" at 164.472,198.124 h1.83
  text "Description" at 183.263,198.124 h1.83
  text "Hole Tolerance (+)" at 204.949,198.124 h1.83
  text "Hole Tolerance (-)" at 238.822,198.124 h1.83
  text "3" at 9.576,194.314 h1.52
  text "86.61mil (2.200mm)" at 24.304,194.314 h1.52
  text "PTH" at 52.236,194.314 h1.52
  text "Round" at 65.085,194.314 h1.52
  text "Top Layer - Bottom Layer" at 83.724,194.314 h1.52
  text "Pad" at 121.812,194.314 h1.52
  text "Rounded Rectangle" at 136.794,194.314 h1.52
  text "(Mixed)" at 164.472,194.314 h1.52
  text "5" at 9.576,190.504 h1.52
  text "14.00mil (0.356mm)" at 24.304,190.504 h1.52
  text "PTH" at 52.236,190.504 h1.52
  text "Round" at 65.085,190.504 h1.52
  text "Top Layer - Bottom Layer" at 83.724,190.504 h1.52
  text "Via" at 121.812,190.504 h1.52
  text "Rounded" at 136.794,190.504 h1.52
  text "v61h36m0mx0" at 164.472,190.504 h1.52
  text "6" at 9.576,186.694 h1.52
  text "51.18mil (1.300mm)" at 24.304,186.694 h1.52
  text "PTH" at 52.236,186.694 h1.52
  text "Round" at 65.085,186.694 h1.52
  text "Top Layer - Bottom Layer" at 83.724,186.694 h1.52
  text "Pad" at 121.812,186.694 h1.52
  text "(Mixed)" at 136.794,186.694 h1.52
  text "(Mixed)" at 164.472,186.694 h1.52
  text "8" at 9.576,182.884 h1.52
  text "30.00mil (0.762mm)" at 24.304,182.884 h1.52
  text "PTH" at 52.236,182.884 h1.52
  text "Round" at 65.085,182.884 h1.52
  text "Top Layer - Bottom Layer" at 83.724,182.884 h1.52
  text "Pad" at 121.812,182.884 h1.52
  text "(Mixed)" at 136.794,182.884 h1.52
  text "(Mixed)" at 164.472,182.884 h1.52
  text "12" at 9.576,179.074 h1.52
  text "47.24mil (1.200mm)" at 24.304,179.074 h1.52
  text "PTH" at 52.236,179.074 h1.52
  text "Round" at 65.085,179.074 h1.52
  text "Top Layer - Bottom Layer" at 83.724,179.074 h1.52
  text "Pad" at 121.812,179.074 h1.52
  text "Rounded" at 136.794,179.074 h1.52
  text "(Mixed)" at 164.472,179.074 h1.52
  text "12" at 9.576,175.264 h1.52
  text "63.00mil (1.600mm)" at 24.304,175.264 h1.52
  text "PTH" at 52.236,175.264 h1.52
  text "Round" at 65.085,175.264 h1.52
  text "Top Layer - Bottom Layer" at 83.724,175.264 h1.52
  text "Pad" at 121.812,175.264 h1.52
  text "Rounded" at 136.794,175.264 h1.52
  text "c221h160" at 164.472,175.264 h1.52
  text "40" at 9.576,171.454 h1.52
  text "40.16mil (1.020mm)" at 24.304,171.454 h1.52
  text "PTH" at 52.236,171.454 h1.52
  text "Round" at 65.085,171.454 h1.52
  text "Top Layer - Bottom Layer" at 83.724,171.454 h1.52
  text "Pad" at 121.812,171.454 h1.52
  text "(Mixed)" at 136.794,171.454 h1.52
  text "(Mixed)" at 164.472,171.454 h1.52
  text "225" at 9.576,167.644 h1.52
  text "16.00mil (0.406mm)" at 24.304,167.644 h1.52
  text "PTH" at 52.236,167.644 h1.52
  text "Round" at 65.085,167.644 h1.52
  text "Top Layer - Bottom Layer" at 83.724,167.644 h1.52
  text "Via" at 121.812,167.644 h1.52
  text "Rounded" at 136.794,167.644 h1.52
  text "v86h41m0mx0" at 164.472,167.644 h1.52
  text "311 Total" at 9.576,163.834 h1.52
  text ".Layer_Name" at 14.656,-21.806 h1.52
M17 Embedded Cavity:
  text ".Layer_Name" at 14.656,-21.806 h1.52
M18 Embedded Assembly:
  text ".Layer_Name" at 14.656,-21.806 h1.52
M19 Embedded Keepout:
  text ".Layer_Name" at 14.656,-21.806 h1.52

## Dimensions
73.884,64.116 to 73.884,23.476 on M2 Board Dimensions
0,-10.16 to 25.4,-10.16 on M2 Board Dimensions
0,0 to 0,87.63 on M2 Board Dimensions
0,0 to 125.73,0 on M2 Board Dimensions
